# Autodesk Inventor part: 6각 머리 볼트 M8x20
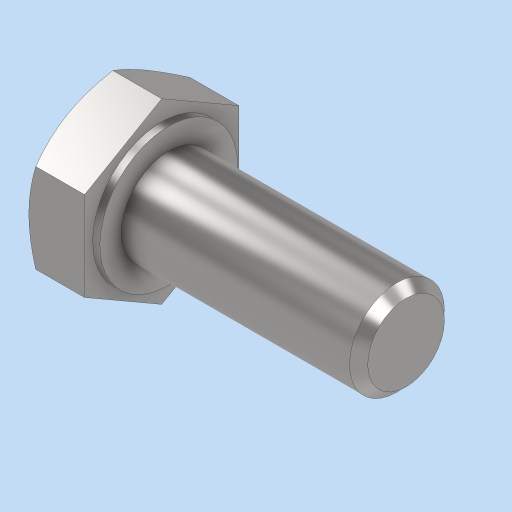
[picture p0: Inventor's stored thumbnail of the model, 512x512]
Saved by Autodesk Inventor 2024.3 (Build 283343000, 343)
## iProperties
Created: 2025-11
Part Number: 6각 머리 볼트 M8x20
Material: 강철, 연강
Description: 6각 머리 볼트 및 6각 머리 나사
Document SubType Name: Modeling
Designer: PC2-03
Density: 7.85 g/cm^3
Appearance: 기본값
Author: jhkim
Sending System: Autodesk Inventor 2026
Preprocessor: ST-DEVELOPER v20.1
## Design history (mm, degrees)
feature "Solid1"
node "솔리드1"
